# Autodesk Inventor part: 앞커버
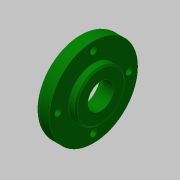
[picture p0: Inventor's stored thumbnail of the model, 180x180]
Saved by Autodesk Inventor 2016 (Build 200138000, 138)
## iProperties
Created: 2015-12
Part Number: 앞커버
Document SubType Name: Modeling
Designer: mdu
Density: 2.71 g/cm^3
Material: 알루미늄 6061
Appearance: 진녹색
Mass: 71.0233 g
Surface Area: 94.1932 cm^2
Volume: 26.2079 cm^3
Author: mdu
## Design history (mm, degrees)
sketch "스케치1"
  geometry: L1 (-7.5, 0)-(7.5, 0); L2 (-7.5, 0)-(-7.5, 31); L3 (-7.5, 31)-(2.5, 31); L4 (2.5, 31)-(2.5, 17.5); L5 (2.5, 17.5)-(7.5, 17.5); L6 (7.5, 17.5)-(7.5, 0); 2 further points
  constraints: 12 end point, 3 perpendicular, 1 coincident, 1 horizontal, 1 midpoint, 1 parallel
  dimensions: "d0" = 15 distance of L1.start L1.end; "d1" = 62 diameter of L3 L1; "d2" = 35 diameter of L5 L1; "d5" = 10 distance of L2.end L3.end
revolve "회전1" sketch "스케치1" stored, may be unused: angle "d6" = 90 deg
sketch "스케치2" dims "d42" = 50
  geometry: 3 further points
  constraints: 2 vertical alignment, 1 coincident, 2 other
hole "구멍1" sketch "스케치2" at (0, 25) diameter "d8" = 4.5; stored, may be unused: countersink angle "d12" = 90 deg, drill point angle "d14" = 118 deg; dims "d9" = 6, "d10" = 8, "d11" = 4.4, "d13" = 8
hole "구멍2" diameter "d20" = 18; stored, may be unused: countersink angle "d24" = 90 deg, drill point angle "d26" = 0 deg; dims "d18" = 10, "d19" = 10, "d21" = 6, "d22" = 8, "d23" = 4.4, "d25" = 8
hole "구멍3" diameter "d34" = 30; stored, may be unused: countersink angle "d38" = 90 deg, drill point angle "d40" = 0 deg; dims "d32" = 10, "d33" = 10, "d35" = 6, "d36" = 4, "d37" = 2, "d39" = 7.3
fillet "모깎기1" dims "d27" = 3, "d41" = 0.3
chamfer "모따기1" distance "d29" = 0.7; stored, may be unused: second distance "d30" = 2, angle "d31" = 30 deg
chamfer "모따기2" distance "d44" = 1; stored, may be unused: second distance "d45" = 2, angle "d46" = 45 deg
node "솔리드1"
pattern_circular "원형 패턴1" dims angle "d16" = 360 deg
